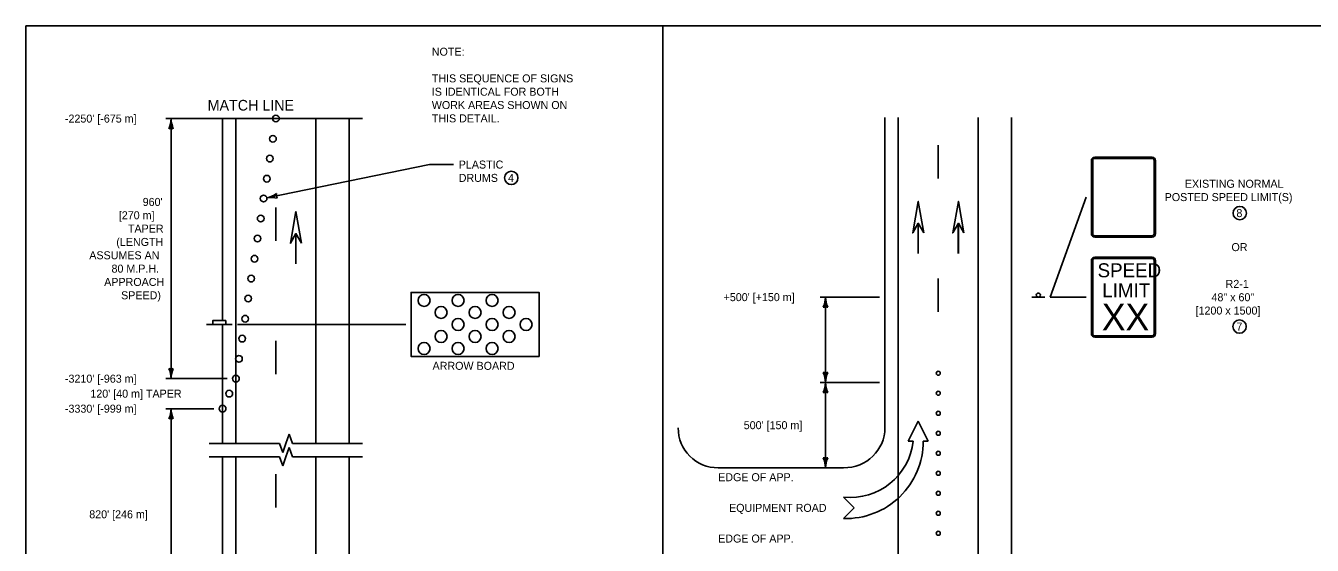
# Model space of a CAD drawing. Extents: x 49991.4 to 50021, y 49987.6 to 50011.4.
# Drawn here: x 49999.38 to 50009.03, y 49995.1 to 49999 of the extents above; entities that cross this region are included whole.
import ezdxf

# ---------------------------------------------------------------- set-up
doc = ezdxf.new("R2010")
doc.units = 0
for name, color, linetype in [('Level 1', 7, 'Continuous'), ('Level 2', 7, 'Continuous'), ('Level 3', 7, 'Continuous'), ('Level 6', 7, 'Continuous')]:
    doc.layers.add(name, color=color, linetype=linetype)

msp = doc.modelspace()

# ---------------------------------------------------------------- linework, layer by layer
at = {"layer": 'Level 1'}
for p, q in [((50000.8598, 49996.7897), (50000.8598, 49998.303)), ((50000.9598, 49995.8676), (50000.9598, 49998.303)), ((50001.5598, 49995.8676), (50001.5598, 49998.303)), ((50001.8098, 49995.8676), (50001.8098, 49998.303)), ((50005.8261, 49995.9842), (50005.8261, 49998.3116)), ((50005.9261, 49989.324), (50005.9261, 49998.3116)), ((50006.5261, 49989.324), (50006.5261, 49998.3116)), ((50006.7761, 49989.324), (50006.7761, 49998.3116)), ((50006.2261, 49997.8534), (50006.2261, 49998.1034)), ((50007.3741, 49997.4393), (50007.3741, 49997.9893)), ((50007.3841, 49997.4393), (50007.3841, 49997.9893)), ((50007.3991, 49998.0143), (50007.8291, 49998.0143)), ((50007.3991, 49998.0043), (50007.8291, 49998.0043)), ((50007.8441, 49997.9893), (50007.8441, 49997.4393)), ((50007.8541, 49997.9893), (50007.8541, 49997.4393)), ((50001.2598, 49997.386), (50001.2598, 49997.636)), ((50006.0761, 49997.292), (50006.0761, 49997.518)), ((50006.0764, 49997.292), (50006.0764, 49997.518)), ((50006.3761, 49997.292), (50006.3761, 49997.518)), ((50006.3764, 49997.292), (50006.3764, 49997.518)), ((50001.4095, 49997.215), (50001.4095, 49997.4409)), ((50001.4098, 49997.215), (50001.4098, 49997.4409)), ((50007.8291, 49997.4243), (50007.3991, 49997.4243)), ((50007.8291, 49997.4143), (50007.3991, 49997.4143)), ((50007.3741, 49996.6893), (50007.3741, 49997.2393)), ((50007.3841, 49996.6893), (50007.3841, 49997.2393)), ((50007.3991, 49997.2643), (50007.8291, 49997.2643)), ((50007.3991, 49997.2543), (50007.8291, 49997.2543)), ((50007.8441, 49997.2393), (50007.8441, 49996.6893)), ((50007.8541, 49997.2393), (50007.8541, 49996.6893)), ((50006.2261, 49996.8534), (50006.2261, 49997.1034)), ((50007.0241, 49996.9642), (50006.9281, 49996.9642)), ((50000.7388, 49996.7593), (50000.9308, 49996.7593)), ((50000.8598, 49995.8676), (50000.8598, 49996.7593)), ((50001.2598, 49996.386), (50001.2598, 49996.636)), ((50007.8291, 49996.6743), (50007.3991, 49996.6743)), ((50007.8291, 49996.6643), (50007.3991, 49996.6643)), ((50006.001, 49995.8842), (50006.076, 49996.0342)), ((50006.076, 49996.0342), (50006.001, 49995.8842)), ((50006.076, 49996.0342), (50006.151, 49995.8842)), ((50006.151, 49995.8842), (50006.076, 49996.0342)), ((50006.001, 49995.8842), (50006.0385, 49995.8842)), ((50006.001, 49995.8842), (50006.0385, 49995.8842)), ((50006.1135, 49995.8842), (50006.151, 49995.8842)), ((50000.8598, 49989.1514), (50000.8598, 49995.7676)), ((50000.9598, 49989.1514), (50000.9598, 49995.7676)), ((50001.5598, 49989.1514), (50001.5598, 49995.7676)), ((50001.8098, 49989.1514), (50001.8098, 49995.7676)), ((50004.5755, 49995.6842), (50005.5161, 49995.6842)), ((50001.2598, 49995.386), (50001.2598, 49995.636)), ((50005.5163, 49995.4642), (50005.5963, 49995.3842)), ((50005.5163, 49995.4642), (50005.5963, 49995.3842)), ((50005.5963, 49995.3842), (50005.5163, 49995.3042)), ((50005.5963, 49995.3842), (50005.5163, 49995.3042))]:
    msp.add_line(p, q, dxfattribs=at)
for points in [[(49999.3835, 49998.9992), (50016.7501, 49998.9992), (50016.7501, 49987.7988), (49999.3835, 49987.7988)], [(50001.4515, 49997.3686), (50001.4098, 49997.6051), (50001.3679, 49997.3686), (50001.4098, 49997.4408)], [(50006.1181, 49997.4456), (50006.0764, 49997.6822), (50006.0345, 49997.4456), (50006.0764, 49997.5178)], [(50006.4181, 49997.4456), (50006.3764, 49997.6822), (50006.3345, 49997.4456), (50006.3764, 49997.5178)], [(50003.2326, 49996.5193), (50002.2726, 49996.5193), (50002.2726, 49996.9993), (50003.2326, 49996.9993)], [(50003.2326, 49996.5193), (50002.2726, 49996.5193), (50002.2726, 49996.9993), (50003.2326, 49996.9993)], [(50000.8828, 49996.7897), (50000.7868, 49996.7897), (50000.7868, 49996.7593), (50000.8828, 49996.7593)]]:
    msp.add_lwpolyline(points, close=True, dxfattribs=at)
for centre, radius in [((50001.2598, 49998.303), 0.025), ((50001.2371, 49998.1517), 0.025), ((50001.2138, 49998.003), 0.025), ((50001.1912, 49997.8525), 0.025), ((50001.1674, 49997.7033), 0.025), ((50001.1453, 49997.5535), 0.025), ((50001.121, 49997.4032), 0.025), ((50001.0983, 49997.2523), 0.025), ((50001.0745, 49997.1031), 0.025), ((50001.0518, 49996.9538), 0.025), ((50002.3701, 49996.9393), 0.045), ((50002.3701, 49996.9393), 0.045), ((50002.6251, 49996.9393), 0.045), ((50002.6251, 49996.9393), 0.045), ((50002.8801, 49996.9393), 0.045), ((50002.8801, 49996.9393), 0.045), ((50006.9761, 49996.9794), 0.0152), ((50001.0289, 49996.8025), 0.025), ((50002.4976, 49996.8493), 0.045), ((50002.4976, 49996.8493), 0.045), ((50002.7526, 49996.8493), 0.045), ((50002.7526, 49996.8493), 0.045), ((50003.0076, 49996.8493), 0.045), ((50003.0076, 49996.8493), 0.045), ((50002.6251, 49996.7593), 0.045), ((50002.6251, 49996.7593), 0.045), ((50002.8801, 49996.7593), 0.045), ((50002.8801, 49996.7593), 0.045), ((50003.1351, 49996.7593), 0.045), ((50003.1351, 49996.7593), 0.045), ((50001.0059, 49996.653), 0.025), ((50002.4976, 49996.6693), 0.045), ((50002.4976, 49996.6693), 0.045), ((50002.7526, 49996.6693), 0.045), ((50002.7526, 49996.6693), 0.045), ((50003.0076, 49996.6693), 0.045), ((50003.0076, 49996.6693), 0.045), ((50002.3701, 49996.5793), 0.045), ((50002.3701, 49996.5793), 0.045), ((50002.6251, 49996.5793), 0.045), ((50002.6251, 49996.5793), 0.045), ((50002.8801, 49996.5793), 0.045), ((50002.8801, 49996.5793), 0.045), ((50000.9826, 49996.5016), 0.025), ((50000.9598, 49996.353), 0.025), ((50006.2261, 49996.3936), 0.015), ((50000.9098, 49996.2405), 0.025), ((50006.2261, 49996.2436), 0.015), ((50000.8598, 49996.128), 0.025), ((50006.2261, 49996.0936), 0.015), ((50006.2261, 49995.9436), 0.015), ((50006.2261, 49995.7936), 0.015), ((50006.2261, 49995.6436), 0.015), ((50006.2261, 49995.4936), 0.015), ((50006.2261, 49995.3436), 0.015), ((50006.2261, 49995.1936), 0.015)]:
    msp.add_circle(centre, radius, dxfattribs=at)
for centre, radius, start, end in [((50007.3991, 49997.9893), 0.025, 90, 180), ((50007.3991, 49997.9893), 0.015, 90, 180), ((50007.8291, 49997.9893), 0.025, 0, 90), ((50007.8291, 49997.9893), 0.015, 0, 90), ((50007.3991, 49997.4393), 0.025, 180, 270), ((50007.3991, 49997.4393), 0.015, 180, 270), ((50007.8291, 49997.4393), 0.025, 270, 0), ((50007.8291, 49997.4393), 0.015, 270, 0), ((50007.399, 49997.2391), 0.025, 90, 180), ((50007.399, 49997.2391), 0.015, 90, 180), ((50007.829, 49997.2391), 0.025, 0, 90), ((50007.829, 49997.2391), 0.015, 0, 90), ((50007.399, 49996.6891), 0.025, 180, 270), ((50007.399, 49996.6891), 0.015, 180, 270), ((50007.829, 49996.6891), 0.025, 270, 0), ((50007.829, 49996.6891), 0.015, 270, 0), ((50004.5755, 49995.9843), 0.3, 180, 270), ((50005.5645, 49995.939), 0.4772, 264.20503, 353.41369), ((50005.5331, 49995.8844), 0.5804, 268.33965, 359.98618), ((50005.5645, 49995.939), 0.4772, 264.20503, 353.41369), ((50005.5331, 49995.8844), 0.5804, 268.33965, 359.98618)]:
    msp.add_arc(centre, radius, start, end, dxfattribs=at)
msp.add_ellipse((50005.5161, 49995.9843), major_axis=(0.31, 0), ratio=0.967994, start_param=4.712389, end_param=6.283185, dxfattribs=at)
at = {"layer": 'Level 2'}
for centre in [(50003.0243, 49997.8584), (50008.4865, 49997.5943), (50008.4852, 49996.7435)]:
    msp.add_circle(centre, 0.05, dxfattribs=at)
at = {"layer": 'Level 3'}
for p, q in [((50004.1614, 49998.9992), (50004.1614, 49987.7988)), ((50000.4732, 49998.303), (50000.4732, 49996.353)), ((50001.1918, 49997.7083), (50002.4102, 49997.9584)), ((50002.4102, 49997.9584), (50002.5902, 49997.9584)), ((50007.3341, 49997.7142), (50007.0641, 49996.9642)), ((50005.3407, 49996.9642), (50005.7861, 49996.9642)), ((50005.3807, 49996.3242), (50005.3807, 49996.9642)), ((50007.0641, 49996.9642), (50007.3341, 49996.9642)), ((50000.9708, 49996.7593), (50002.2326, 49996.7593)), ((50000.4332, 49996.353), (50000.8948, 49996.353)), ((50005.3407, 49996.3242), (50005.7861, 49996.3242)), ((50005.3807, 49995.6842), (50005.3807, 49996.3242)), ((50000.4332, 49996.128), (50000.7948, 49996.128)), ((50000.4732, 49996.128), (50000.4732, 49994.544))]:
    msp.add_line(p, q, dxfattribs=at)
for centre, radius, start, end in [((50000.2405, 49998.3145), 0.233, 337.92284, 357.17269), ((50000.6953, 49998.3122), 0.2223, 182.36048, 202.54399), ((50000.4732, 49998.1748), 0.0548, 72.13882, 107.86118), ((50001.1383, 49997.9241), 0.2223, 283.94583, 304.12933), ((50001.2273, 49997.4781), 0.233, 79.50818, 98.75803), ((50001.3174, 49997.7341), 0.0548, 173.72416, 209.44653), ((50005.1585, 49996.9734), 0.2223, 337.45601, 357.63952), ((50005.6134, 49996.9757), 0.233, 182.82731, 202.07716), ((50005.3807, 49996.836), 0.0548, 72.13882, 107.86118), ((50000.251, 49996.3438), 0.2223, 2.36048, 22.54399), ((50000.4732, 49996.4812), 0.0548, 252.13882, 287.86118), ((50000.7059, 49996.3415), 0.233, 157.92284, 177.17269), ((50005.3807, 49996.4524), 0.0548, 252.13882, 287.86118), ((50005.148, 49996.3127), 0.233, 2.82731, 22.07716), ((50005.6028, 49996.315), 0.2223, 157.45601, 177.63952), ((50005.1585, 49996.3334), 0.2223, 337.45601, 357.63952), ((50005.3807, 49996.196), 0.0548, 72.13882, 107.86118), ((50005.6134, 49996.3357), 0.233, 182.82731, 202.07716), ((50000.2405, 49996.1395), 0.233, 337.92284, 357.17269), ((50000.6953, 49996.1372), 0.2223, 182.36048, 202.54399), ((50000.4732, 49995.9998), 0.0548, 72.13882, 107.86118), ((50005.3807, 49995.8124), 0.0548, 252.13882, 287.86118), ((50005.148, 49995.6727), 0.233, 2.82731, 22.07716), ((50005.6028, 49995.675), 0.2223, 157.45601, 177.63952)]:
    msp.add_arc(centre, radius, start, end, dxfattribs=at)
at = {"layer": 'Level 6'}
for p, q in [((50001.9098, 49998.303), (50000.4332, 49998.303)), ((50001.2862, 49995.8676), (50000.7598, 49995.8676)), ((50001.2862, 49995.8676), (50001.3105, 49995.7991)), ((50001.3348, 49995.8676), (50001.3105, 49995.7991)), ((50001.3591, 49995.9361), (50001.3348, 49995.8676)), ((50001.3591, 49995.9361), (50001.3834, 49995.8676)), ((50001.9098, 49995.8676), (50001.3834, 49995.8676)), ((50001.2862, 49995.7676), (50000.7598, 49995.7676)), ((50001.2862, 49995.7676), (50001.3105, 49995.6991)), ((50001.3348, 49995.7676), (50001.3105, 49995.6991)), ((50001.3591, 49995.8361), (50001.3348, 49995.7676)), ((50001.3591, 49995.8361), (50001.3834, 49995.7676)), ((50001.9098, 49995.7676), (50001.3834, 49995.7676))]:
    msp.add_line(p, q, dxfattribs=at)

# ---------------------------------------------------------------- texts
at = {"layer": 'Level 1'}
for s, height, p in [('SPEED', 0.10512, (50007.4204, 49997.113)), ('LIMIT', 0.10512, (50007.4558, 49996.9628)), ('XX', 0.1989, (50007.4526, 49996.7156))]:
    msp.add_text(s, height=height, dxfattribs=at).set_placement(p)
at = {"layer": 'Level 2'}
for s, height, p in [('NOTE:', 0.06, (50002.4283, 49998.7745)), ('THIS SEQUENCE OF SIGNS', 0.06, (50002.4283, 49998.5745)), ('IS IDENTICAL FOR BOTH', 0.06, (50002.4283, 49998.4745)), ('MATCH LINE', 0.08, (50000.7476, 49998.363)), ('WORK AREAS SHOWN ON', 0.06, (50002.4283, 49998.3745)), ("-2250' [-675 m]", 0.06, (49999.6774, 49998.273)), ('THIS DETAIL.', 0.06, (50002.4283, 49998.2745)), ('PLASTIC', 0.06, (50002.6302, 49997.9284)), ('DRUMS', 0.06, (50002.6302, 49997.8284)), ('4', 0.06, (50003.0003, 49997.8284)), ('EXISTING NORMAL', 0.06, (50008.0748, 49997.7843)), ("960'", 0.06, (50000.2604, 49997.6481)), ('POSTED SPEED LIMIT(S)', 0.06, (50007.9235, 49997.6843)), ('[270 m]', 0.06, (50000.0816, 49997.5481)), ('8', 0.06, (50008.4615, 49997.5643)), ('TAPER', 0.06, (50000.1498, 49997.4481)), ('(LENGTH', 0.06, (50000.0627, 49997.3481)), ('OR', 0.06, (50008.4244, 49997.3093)), ('ASSUMES AN', 0.06, (49999.86, 49997.2481)), ('80 M.P.H.', 0.06, (50000.0268, 49997.1481)), ('APPROACH', 0.06, (49999.9717, 49997.0481)), ('R2-1', 0.06, (50008.3802, 49997.0335)), ('SPEED)', 0.06, (50000.0985, 49996.9481)), ("+500' [+150 m]", 0.06, (50004.6161, 49996.9342)), ('48" x 60"', 0.06, (50008.2747, 49996.9335)), ('[1200 x 1500]', 0.06, (50008.1552, 49996.8335)), ('7', 0.06, (50008.4614, 49996.7135)), ('ARROW BOARD', 0.06, (50002.4339, 49996.4193)), ("-3210' [-963 m]", 0.06, (49999.6774, 49996.323)), ("120' [40 m] TAPER", 0.06, (49999.8682, 49996.2105)), ("-3330' [-999 m]", 0.06, (49999.6774, 49996.098)), ("500' [150 m]", 0.06, (50004.7673, 49995.9742)), ('EDGE OF APP.', 0.06, (50004.5755, 49995.5842)), ('EQUIPMENT ROAD', 0.06, (50004.6572, 49995.3542)), ("820' [246 m]", 0.06, (49999.8598, 49995.306)), ('EDGE OF APP.', 0.06, (50004.5755, 49995.1242))]:
    msp.add_text(s, height=height, dxfattribs=at).set_placement(p)

doc.saveas('drawing.dxf')
